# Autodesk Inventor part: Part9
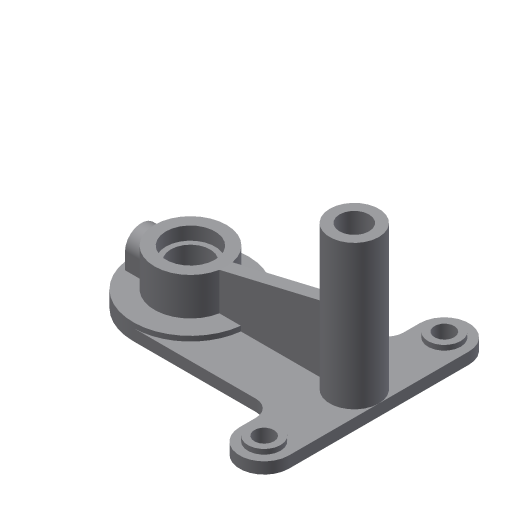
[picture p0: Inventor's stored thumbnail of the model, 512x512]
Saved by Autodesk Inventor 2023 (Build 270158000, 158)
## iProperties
Created: 2001-12
Part Number: Part9
Document SubType Name: Modeling
Density: 1 g/cm^3
Material: Generic
Appearance: Default
Control State: 0
Master: False
Checked Out: False
Shininess: 77.0
Length Units: 11269
Angle Units: 11279
Time Units: 11290
Mass Units: 11283
Length Display Precision: 3
Angle Display Precision: 2
Density: 0.0
Volumn: 0.0
Area: 0.0
PropertySet Name: Model Information
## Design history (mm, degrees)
sketch "Sketch1"
  geometry: L1 (46.121, -53.4)-(46.121, 56.6); L2 (16.121, 56.6)-(16.121, 36.6); L3 (16.121, 36.6)-(-68.879, 36.6); L4 (-68.879, -33.4)-(16.121, -33.4); L5 (16.121, -33.4)-(16.121, -53.4); A1 r 15 centre (31.121, 56.6) between (46.121, 56.6) and (16.121, 56.6); A2 r 35 centre (-68.879, 1.6) between (-68.879, 36.6) and (-68.879, -33.4); A3 r 15 centre (31.121, -53.4) between (16.121, -53.4) and (46.121, -53.4)
  constraints: 10 end point, 6 point on circle, 5 tangent, 3 centre point, 3 parallel, 2 equal length, 1 equal radius, 1 perpendicular, 1 vertical
  dimensions: "d0" = 15 radius of A1; "d1" = 110 distance of L1.start L1.end; "d2" = 100 horizontal distance of A3.centre A2.centre; "d3" = 35 radius of A2
extrude "Extrusion1" new body sketch "Sketch1" distance "d4" = 7; taper "d5" = 0 deg
sketch "Sketch2"
  geometry: C1 r 10 at (31.121, 56.6); C2 r 10 at (31.121, -53.4); C3 r 35 at (-68.879, 1.6); A1 r 35 centre (-68.879, 1.6) between (-68.879, 36.6) and (-68.879, -33.4) reference; A2 r 15 centre (31.121, 56.6) between (46.121, 56.6) and (16.121, 56.6) reference; A3 r 15 centre (31.121, -53.4) between (16.121, -53.4) and (46.121, -53.4) reference
  constraints: 3 centre point, 3 concentric, 2 equal radius
  dimensions: "d45" = 20 diameter of C1
extrude "Extrusion2" join sketch "Sketch2" distance "d6" = 3; taper "d7" = 0 deg
sketch "Sketch3"
  geometry: C1 r 22 at (0, 0); 1 further point
  constraints: 1 centre point, 1 coincident
  dimensions: "d8" = 44 diameter of C1
extrude "Extrusion3" join sketch "Sketch3" distance "d9" = 23; taper "d10" = 0 deg
sketch "Sketch4"
  geometry: L1 (46.121, 56.6)-(46.121, -53.4) reference; L2 (-68.879, 36.6)-(16.121, 36.6) reference; C1 r 15 at (31.121, 1.6)
  constraints: 1 centre point
  dimensions: "d11" = 30 diameter of C1; "d12" = 15 distance from line of L1 C1.centre; "d13" = 35 distance from line of L2 C1.centre
extrude "Extrusion4" join sketch "Sketch4" distance "d14" = 88; taper "d15" = 0 deg
workplane "Work Plane1"
sketch "Sketch5"
  geometry: L1 (22, 33.1)-(85, 48); L2 (0, 7)-(35, 7) reference; L3 (85, 0)-(85, 7) reference; L4 (115, 0)-(115, 7) reference; L5 (115, 0)-(85, 0) reference
  constraints: 2 end point
  dimensions: "d17" = 26.1 distance from line of L2 L1.start; "d18" = 63 distance from line of L3 L1.start; "d19" = 30 distance from line of L4 L1.end; "d20" = 48 distance from line of L5 L1.end
feature "Rib1" sketch "Sketch5" dims "d21" = 1, "d22" = 8
workplane "Work Plane2"
workplane "Work Plane3"
sketch "Sketch7"
  geometry: L1 (10, 0)-(10, 10); L2 (-10, 10)-(-10, 0); L3 (-10, 0)-(10, 0); L4 (55, -10)-(55, -3) reference; A1 r 10 centre (0, 10) between (10, 10) and (-10, 10); 2 further points
  constraints: 6 end point, 2 point on circle, 2 tangent, 1 centre point, 1 parallel, 1 perpendicular, 1 vertical
  dimensions: "d30" = 10 radius of A1; "d34" = 55 distance from line of L4 A1.centre; "d35" = 10 distance of L1.start L1.end
extrude "Extrusion6" join sketch "Sketch7" stored distance "d36" = 88; taper "d37" = 0 deg
sketch "Sketch8"
  geometry: C1 r 10 at (0, 0) reference
hole "Hole1" sketch "Sketch8" at (0, 0) diameter "d38" = 12; stored, may be unused: countersink angle "d42" = 82 deg, drill point angle "d44" = 118 deg; dims "d39" = 6, "d40" = 4, "d41" = 2, "d43" = 8
mirror "Mirror1"
sketch "Sketch9"
  geometry: C1 r 10 at (0, 0)
  constraints: 1 centre point
hole "Hole2" sketch "Sketch9" at (0, 0) diameter "d52" = 18; stored, may be unused: drill point angle "d47" = 118 deg, countersink angle "d48" = 82 deg; dims "d46" = 6, "d49" = 2, "d50" = 4, "d51" = 8
sketch "Sketch10"
  geometry: C1 r 10 at (0, 0)
  constraints: 1 centre point
hole "Hole3" sketch "Sketch10" at (0, 0) diameter "d59" = 24; stored, may be unused: drill point angle "d54" = 118 deg, countersink angle "d55" = 82 deg; dims "d53" = 6, "d56" = 8, "d57" = 30, "d58" = 8
sketch "Sketch11"
  geometry: C1 r 10 at (0, 0)
  constraints: 1 centre point
hole "Hole4" sketch "Sketch11" at (0, 0) diameter "d66" = 10; stored, may be unused: drill point angle "d61" = 0 deg, countersink angle "d62" = 82 deg; dims "d60" = 6, "d63" = 2, "d64" = 4, "d65" = 8
fillet "Fillet1" dims "d67" = 10
body "Solid1"
other parameters: "d16" = -35, "d29" = -8
